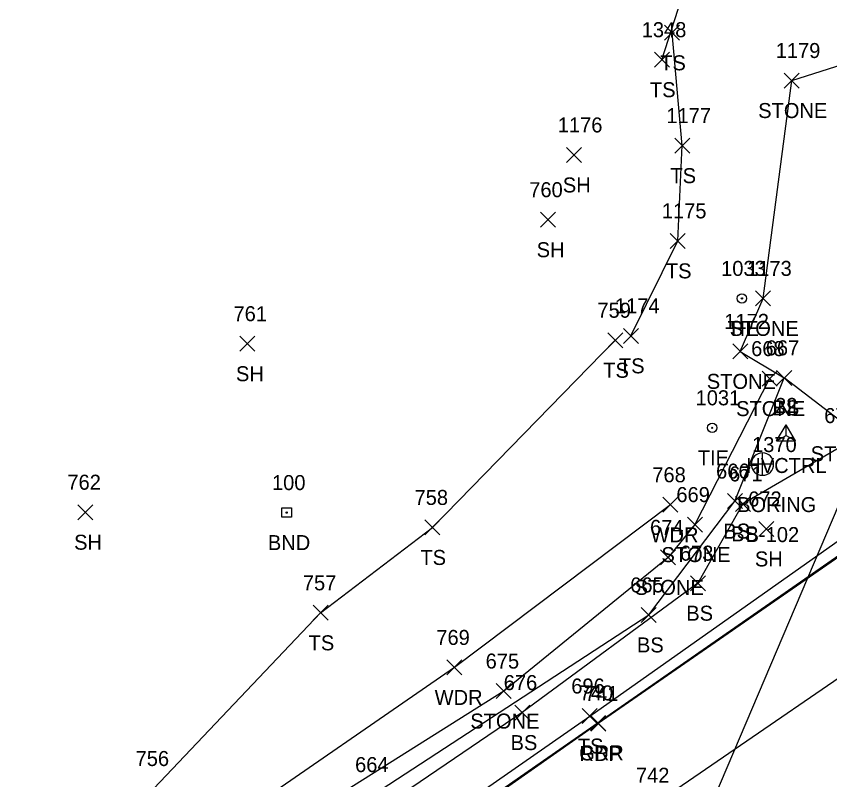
# Model space of a CAD drawing. Extents: x 1528286 to 1556263, y 492387 to 508952.
# Drawn here: x 1528575.8 to 1528684.2, y 492794 to 492895.8 of the extents above; entities that cross this region are included whole.
import ezdxf

# ---------------------------------------------------------------- set-up
doc = ezdxf.new("R2010")
doc.units = 0
for name, color, linetype in [('C_A', 7, 'Continuous'), ('C_I', 7, 'Continuous'), ('CBP', 7, 'Continuous'), ('CPSM', 7, 'Continuous'), ('DCP', 7, 'Continuous'), ('G_A', 7, 'Continuous'), ('G_C', 7, 'Continuous'), ('G_I', 7, 'Continuous'), ('GA_P', 7, 'Continuous'), ('L_A', 7, 'Continuous'), ('L_I', 7, 'Continuous'), ('L_TIC', 7, 'Continuous'), ('LASF', 7, 'Continuous'), ('LAWA', 7, 'Continuous'), ('LELB', 7, 'Continuous'), ('Level 18', 7, 'Continuous'), ('M_A', 7, 'Continuous'), ('M_I', 7, 'Continuous'), ('P_A', 7, 'Continuous'), ('P_I', 7, 'Continuous'), ('P_TIC', 7, 'Continuous'), ('PET', 7, 'Continuous'), ('PRC', 7, 'Continuous'), ('R_A', 7, 'Continuous'), ('R_I', 7, 'Continuous'), ('R_TIC', 7, 'Continuous'), ('RGR', 7, 'Continuous')]:
    doc.layers.add(name, color=color, linetype=linetype)

msp = doc.modelspace()

# ---------------------------------------------------------------- linework, layer by layer
at = {"layer": 'CBP'}
for centre, radius in [((1528672.47, 492858.2), 0.625), ((1528672.47, 492858.2), 0.625), ((1528672.47, 492858.2), 0.0833), ((1528672.47, 492858.2), 0.0833), ((1528668.51, 492840.95), 0.625), ((1528668.51, 492840.95), 0.625), ((1528668.51, 492840.95), 0.0833), ((1528668.51, 492840.95), 0.0833)]:
    msp.add_circle(centre, radius, dxfattribs=at)
at = {"layer": 'CPSM'}
for p, q in [((1528677.1, 492839.21), (1528678.35, 492841.37)), ((1528677.1, 492839.21), (1528678.35, 492841.37)), ((1528679.6, 492839.21), (1528678.35, 492841.37)), ((1528678.36, 492839.93), (1528678.35, 492841.37)), ((1528679.6, 492839.21), (1528678.35, 492841.37)), ((1528678.36, 492839.93), (1528678.35, 492841.37)), ((1528677.1, 492839.21), (1528678.36, 492839.93)), ((1528677.1, 492839.21), (1528678.36, 492839.93)), ((1528678.36, 492839.93), (1528678.36, 492839.93)), ((1528678.36, 492839.93), (1528679.6, 492839.21)), ((1528678.36, 492839.93), (1528678.36, 492839.93)), ((1528678.36, 492839.93), (1528679.6, 492839.21)), ((1528677.1, 492839.21), (1528679.6, 492839.21)), ((1528677.1, 492839.21), (1528679.6, 492839.21))]:
    msp.add_line(p, q, dxfattribs=at)
at = {"layer": 'DCP'}
msp.add_lwpolyline([(1528644.2, 492733.84), (1528697.66, 492859.59)], dxfattribs=at)
msp.add_lwpolyline([(1528644.2, 492733.84), (1528697.66, 492859.59)], dxfattribs=at)
at = {"layer": 'GA_P'}
for p, q in [((1528675.2, 492836.12), (1528675.2, 492837.62)), ((1528675.2, 492836.12), (1528675.2, 492837.62)), ((1528675.2, 492836.12), (1528673.7, 492836.12)), ((1528675.2, 492836.12), (1528673.7, 492836.12)), ((1528676.7, 492836.12), (1528675.2, 492836.12)), ((1528675.2, 492834.62), (1528675.2, 492836.12)), ((1528676.7, 492836.12), (1528675.2, 492836.12)), ((1528675.2, 492834.62), (1528675.2, 492836.12))]:
    msp.add_line(p, q, dxfattribs=at)
for start, end in [(90, 180), (90, 180), (0, 90), (0, 90), (180, 270), (180, 270), (270, 0), (270, 0)]:
    msp.add_arc((1528675.2, 492836.12), 1.5, start, end, dxfattribs=at)
at = {"layer": 'L_TIC'}
for points in [[(1528662.17, 492892.6), (1528664.17, 492894.6)], [(1528664.17, 492892.6), (1528662.17, 492894.6)], [(1528662.17, 492892.6), (1528664.17, 492894.6)], [(1528664.17, 492892.6), (1528662.17, 492894.6)], [(1528660.81, 492889.02), (1528662.81, 492891.02)], [(1528662.81, 492889.02), (1528660.81, 492891.02)], [(1528660.81, 492889.02), (1528662.81, 492891.02)], [(1528662.81, 492889.02), (1528660.81, 492891.02)], [(1528678.1, 492886.24), (1528680.1, 492888.24)], [(1528680.1, 492886.24), (1528678.1, 492888.24)], [(1528678.1, 492886.24), (1528680.1, 492888.24)], [(1528680.1, 492886.24), (1528678.1, 492888.24)], [(1528663.53, 492877.56), (1528665.53, 492879.56)], [(1528665.53, 492877.56), (1528663.53, 492879.56)], [(1528663.53, 492877.56), (1528665.53, 492879.56)], [(1528665.53, 492877.56), (1528663.53, 492879.56)], [(1528649.12, 492876.32), (1528651.12, 492878.32)], [(1528651.12, 492876.32), (1528649.12, 492878.32)], [(1528649.12, 492876.32), (1528651.12, 492878.32)], [(1528651.12, 492876.32), (1528649.12, 492878.32)], [(1528645.64, 492867.69), (1528647.64, 492869.69)], [(1528647.64, 492867.69), (1528645.64, 492869.69)], [(1528645.64, 492867.69), (1528647.64, 492869.69)], [(1528647.64, 492867.69), (1528645.64, 492869.69)], [(1528662.93, 492864.87), (1528664.93, 492866.87)], [(1528664.93, 492864.87), (1528662.93, 492866.87)], [(1528662.93, 492864.87), (1528664.93, 492866.87)], [(1528664.93, 492864.87), (1528662.93, 492866.87)], [(1528674.29, 492857.2), (1528676.29, 492859.2)], [(1528676.29, 492857.2), (1528674.29, 492859.2)], [(1528674.29, 492857.2), (1528676.29, 492859.2)], [(1528676.29, 492857.2), (1528674.29, 492859.2)], [(1528656.68, 492852.21), (1528658.68, 492854.21)], [(1528658.68, 492852.21), (1528656.68, 492854.21)], [(1528656.68, 492852.21), (1528658.68, 492854.21)], [(1528658.68, 492852.21), (1528656.68, 492854.21)], [(1528605.58, 492851.16), (1528607.58, 492853.16)], [(1528607.58, 492851.16), (1528605.58, 492853.16)], [(1528605.58, 492851.16), (1528607.58, 492853.16)], [(1528607.58, 492851.16), (1528605.58, 492853.16)], [(1528654.59, 492851.62), (1528656.59, 492853.62)], [(1528656.59, 492851.62), (1528654.59, 492853.62)], [(1528654.59, 492851.62), (1528656.59, 492853.62)], [(1528656.59, 492851.62), (1528654.59, 492853.62)], [(1528671.24, 492850.14), (1528673.24, 492852.14)], [(1528673.24, 492850.14), (1528671.24, 492852.14)], [(1528671.24, 492850.14), (1528673.24, 492852.14)], [(1528673.24, 492850.14), (1528671.24, 492852.14)], [(1528677.1, 492846.61), (1528679.1, 492848.61)], [(1528679.1, 492846.61), (1528677.1, 492848.61)], [(1528677.1, 492846.61), (1528679.1, 492848.61)], [(1528679.1, 492846.61), (1528677.1, 492848.61)], [(1528675.16, 492846.51), (1528677.16, 492848.51)], [(1528677.16, 492846.51), (1528675.16, 492848.51)], [(1528675.16, 492846.51), (1528677.16, 492848.51)], [(1528677.16, 492846.51), (1528675.16, 492848.51)], [(1528661.94, 492829.69), (1528663.94, 492831.69)], [(1528663.94, 492829.69), (1528661.94, 492831.69)], [(1528661.94, 492829.69), (1528663.94, 492831.69)], [(1528663.94, 492829.69), (1528661.94, 492831.69)], [(1528670.54, 492830.18), (1528672.54, 492832.18)], [(1528672.54, 492830.18), (1528670.54, 492832.18)], [(1528670.54, 492830.18), (1528672.54, 492832.18)], [(1528672.54, 492830.18), (1528670.54, 492832.18)], [(1528671.61, 492829.81), (1528673.61, 492831.81)], [(1528673.61, 492829.81), (1528671.61, 492831.81)], [(1528671.61, 492829.81), (1528673.61, 492831.81)], [(1528673.61, 492829.81), (1528671.61, 492831.81)], [(1528584.02, 492828.7), (1528586.02, 492830.7)], [(1528586.02, 492828.7), (1528584.02, 492830.7)], [(1528584.02, 492828.7), (1528586.02, 492830.7)], [(1528586.02, 492828.7), (1528584.02, 492830.7)], [(1528630.23, 492826.67), (1528632.23, 492828.67)], [(1528632.23, 492826.67), (1528630.23, 492828.67)], [(1528630.23, 492826.67), (1528632.23, 492828.67)], [(1528632.23, 492826.67), (1528630.23, 492828.67)], [(1528665.2, 492827.05), (1528667.2, 492829.05)], [(1528667.2, 492827.05), (1528665.2, 492829.05)], [(1528665.2, 492827.05), (1528667.2, 492829.05)], [(1528667.2, 492827.05), (1528665.2, 492829.05)], [(1528674.71, 492826.47), (1528676.71, 492828.47)], [(1528676.71, 492826.47), (1528674.71, 492828.47)], [(1528674.71, 492826.47), (1528676.71, 492828.47)], [(1528676.71, 492826.47), (1528674.71, 492828.47)], [(1528661.64, 492822.68), (1528663.64, 492824.68)], [(1528663.64, 492822.68), (1528661.64, 492824.68)], [(1528661.64, 492822.68), (1528663.64, 492824.68)], [(1528663.64, 492822.68), (1528661.64, 492824.68)], [(1528665.62, 492819.24), (1528667.62, 492821.24)], [(1528667.62, 492819.24), (1528665.62, 492821.24)], [(1528665.62, 492819.24), (1528667.62, 492821.24)], [(1528667.62, 492819.24), (1528665.62, 492821.24)], [(1528615.34, 492815.29), (1528617.34, 492817.29)], [(1528617.34, 492815.29), (1528615.34, 492817.29)], [(1528615.34, 492815.29), (1528617.34, 492817.29)], [(1528617.34, 492815.29), (1528615.34, 492817.29)], [(1528659.05, 492815.01), (1528661.05, 492817.01)], [(1528661.05, 492815.01), (1528659.05, 492817.01)], [(1528659.05, 492815.01), (1528661.05, 492817.01)], [(1528661.05, 492815.01), (1528659.05, 492817.01)], [(1528633.18, 492808.01), (1528635.18, 492810.01)], [(1528635.18, 492808.01), (1528633.18, 492810.01)], [(1528633.18, 492808.01), (1528635.18, 492810.01)], [(1528635.18, 492808.01), (1528633.18, 492810.01)], [(1528639.74, 492804.86), (1528641.74, 492806.86)], [(1528641.74, 492804.86), (1528639.74, 492806.86)], [(1528639.74, 492804.86), (1528641.74, 492806.86)], [(1528641.74, 492804.86), (1528639.74, 492806.86)], [(1528642.21, 492801.99), (1528644.21, 492803.99)], [(1528644.21, 492801.99), (1528642.21, 492803.99)], [(1528642.21, 492801.99), (1528644.21, 492803.99)], [(1528644.21, 492801.99), (1528642.21, 492803.99)], [(1528651.2, 492801.53), (1528653.2, 492803.53)], [(1528653.2, 492801.53), (1528651.2, 492803.53)], [(1528651.2, 492801.53), (1528653.2, 492803.53)], [(1528653.2, 492801.53), (1528651.2, 492803.53)]]:
    msp.add_lwpolyline(points, dxfattribs=at)
at = {"layer": 'LASF'}
for points in [[(1528672.24, 492851.14), (1528675.29, 492858.2), (1528679.1, 492887.24), (1528690.96, 492891.02), (1528695.31, 492889.33), (1528691.61, 492862.53)], [(1528672.24, 492851.14), (1528675.29, 492858.2), (1528679.1, 492887.24), (1528690.96, 492891.02), (1528695.31, 492889.33), (1528691.61, 492862.53)], [(1528672.24, 492851.14), (1528678.1, 492847.61)], [(1528672.24, 492851.14), (1528678.1, 492847.61)], [(1528676.16, 492847.51), (1528666.2, 492828.05), (1528662.64, 492823.68), (1528640.74, 492805.86), (1528611.48, 492787.39), (1528588.51, 492771.6), (1528589.32, 492769.92)], [(1528676.16, 492847.51), (1528666.2, 492828.05), (1528662.64, 492823.68), (1528640.74, 492805.86), (1528611.48, 492787.39), (1528588.51, 492771.6), (1528589.32, 492769.92)], [(1528686.09, 492841.49), (1528678.1, 492847.61)], [(1528686.09, 492841.49), (1528678.1, 492847.61)]]:
    msp.add_lwpolyline(points, dxfattribs=at)
at = {"layer": 'LAWA'}
msp.add_lwpolyline([(1528662.94, 492830.69), (1528634.18, 492809.01), (1528604.19, 492788.28), (1528566.96, 492760.01), (1528530.31, 492736.52), (1528502.64, 492712.53), (1528486.78, 492718.4), (1528471.22, 492734.89)], dxfattribs=at)
msp.add_lwpolyline([(1528662.94, 492830.69), (1528634.18, 492809.01), (1528604.19, 492788.28), (1528566.96, 492760.01), (1528530.31, 492736.52), (1528502.64, 492712.53), (1528486.78, 492718.4), (1528471.22, 492734.89)], dxfattribs=at)
at = {"layer": 'LELB'}
for points in [[(1528511.53, 492702.85), (1528534.14, 492721.31), (1528572.64, 492751.16), (1528586.73, 492763.59), (1528600.5, 492766.35), (1528613.46, 492775.52), (1528652.2, 492802.53), (1528688.62, 492828.26), (1528710.29, 492843.12), (1528742.91, 492866.47), (1528778.71, 492891.27), (1528817.45, 492919.08), (1528857.75, 492946.94), (1528897.37, 492973.98), (1528940.29, 493003.74)], [(1528511.53, 492702.85), (1528534.14, 492721.31), (1528572.64, 492751.16), (1528586.73, 492763.59), (1528600.5, 492766.35), (1528613.46, 492775.52), (1528652.2, 492802.53), (1528688.62, 492828.26), (1528710.29, 492843.12), (1528742.91, 492866.47), (1528778.71, 492891.27), (1528817.45, 492919.08), (1528857.75, 492946.94), (1528897.37, 492973.98), (1528940.29, 493003.74)], [(1528661.81, 492890.02), (1528672.21, 492922.28), (1528667.05, 492924.05), (1528644.6, 492935.3)], [(1528661.81, 492890.02), (1528672.21, 492922.28), (1528667.05, 492924.05), (1528644.6, 492935.3)], [(1528657.68, 492853.21), (1528663.93, 492865.87), (1528664.53, 492878.56), (1528663.17, 492893.6)], [(1528657.68, 492853.21), (1528663.93, 492865.87), (1528664.53, 492878.56), (1528663.17, 492893.6)], [(1528479.27, 492740.39), (1528490.26, 492728.47), (1528495.22, 492727.6), (1528516.65, 492745.84), (1528531.02, 492756.16), (1528553.24, 492773.68), (1528563.71, 492774.04), (1528594.12, 492792.87), (1528616.34, 492816.29), (1528631.23, 492827.67), (1528655.59, 492852.62)], [(1528479.27, 492740.39), (1528490.26, 492728.47), (1528495.22, 492727.6), (1528516.65, 492745.84), (1528531.02, 492756.16), (1528553.24, 492773.68), (1528563.71, 492774.04), (1528594.12, 492792.87), (1528616.34, 492816.29), (1528631.23, 492827.67), (1528655.59, 492852.62)], [(1528476.47, 492733.09), (1528490.63, 492720.26), (1528499.34, 492715.31), (1528510.27, 492713.09), (1528516.41, 492713.29), (1528530.47, 492725.99), (1528568.48, 492754.56), (1528582.5, 492766.12), (1528590.7, 492769.85), (1528623.39, 492792.06), (1528660.05, 492816.01), (1528671.54, 492831.18), (1528678.1, 492847.61)], [(1528476.47, 492733.09), (1528490.63, 492720.26), (1528499.34, 492715.31), (1528510.27, 492713.09), (1528516.41, 492713.29), (1528530.47, 492725.99), (1528568.48, 492754.56), (1528582.5, 492766.12), (1528590.7, 492769.85), (1528623.39, 492792.06), (1528660.05, 492816.01), (1528671.54, 492831.18), (1528678.1, 492847.61)], [(1528685.94, 492838.58), (1528672.61, 492830.81), (1528666.62, 492820.24), (1528643.21, 492802.99), (1528614.9, 492783.77), (1528590.5, 492768.83), (1528580.05, 492763.59), (1528573.99, 492757.65), (1528555.82, 492743.68), (1528531.3, 492723.9), (1528516.93, 492710.51), (1528511.37, 492706.6)], [(1528685.94, 492838.58), (1528672.61, 492830.81), (1528666.62, 492820.24), (1528643.21, 492802.99), (1528614.9, 492783.77), (1528590.5, 492768.83), (1528580.05, 492763.59), (1528573.99, 492757.65), (1528555.82, 492743.68), (1528531.3, 492723.9), (1528516.93, 492710.51), (1528511.37, 492706.6)]]:
    msp.add_lwpolyline(points, dxfattribs=at)
at = {"layer": 'Level 18'}
msp.add_lwpolyline([(1528611.2, 492830.28), (1528612.45, 492830.28), (1528612.45, 492829.03), (1528611.2, 492829.03)], close=True, dxfattribs=at)
msp.add_lwpolyline([(1528611.2, 492830.28), (1528612.45, 492830.28), (1528612.45, 492829.03), (1528611.2, 492829.03)], close=True, dxfattribs=at)
msp.add_circle((1528611.83, 492829.65), 0.0833, dxfattribs=at)
msp.add_circle((1528611.83, 492829.65), 0.0833, dxfattribs=at)
at = {"layer": 'P_TIC'}
for points in [[(1528652.33, 492800.52), (1528654.33, 492802.52)], [(1528654.33, 492800.52), (1528652.33, 492802.52)], [(1528652.33, 492800.52), (1528654.33, 492802.52)], [(1528654.33, 492800.52), (1528652.33, 492802.52)]]:
    msp.add_lwpolyline(points, dxfattribs=at)
at = {"layer": 'PET'}
for points in [[(1528942, 493002.12), (1528898.48, 492972.51), (1528859.28, 492945.34), (1528819.08, 492917.53), (1528787.55, 492894.48), (1528780.46, 492889.94), (1528744.23, 492865.12), (1528711.17, 492841.82), (1528689.56, 492826.66), (1528653.33, 492801.52)], [(1528942, 493002.12), (1528898.48, 492972.51), (1528859.28, 492945.34), (1528819.08, 492917.53), (1528787.55, 492894.48), (1528780.46, 492889.94), (1528744.23, 492865.12), (1528711.17, 492841.82), (1528689.56, 492826.66), (1528653.33, 492801.52)], [(1528653.33, 492801.52), (1528614.2, 492774.09)], [(1528653.33, 492801.52), (1528614.2, 492774.09)]]:
    msp.add_lwpolyline(points, dxfattribs=at)
at = {"layer": 'PRC'}
msp.add_lwpolyline([(1528788.69, 492878.6), (1528752.94, 492854.08), (1528719.05, 492830.75), (1528697.88, 492816.16), (1528660.71, 492790.64)], dxfattribs=at)
msp.add_lwpolyline([(1528788.69, 492878.6), (1528752.94, 492854.08), (1528719.05, 492830.75), (1528697.88, 492816.16), (1528660.71, 492790.64)], dxfattribs=at)
at = {"layer": 'R_TIC'}
for points in [[(1528652.3, 492800.62), (1528654.3, 492802.62)], [(1528654.3, 492800.62), (1528652.3, 492802.62)], [(1528652.3, 492800.62), (1528654.3, 492802.62)], [(1528654.3, 492800.62), (1528652.3, 492802.62)]]:
    msp.add_lwpolyline(points, dxfattribs=at)
at = {"layer": 'RGR'}
for points in [[(1528941.4, 493002.79), (1528898.12, 492973.22), (1528858.97, 492945.9), (1528818.83, 492918.12), (1528780.05, 492890.64), (1528744.15, 492865.31), (1528711.24, 492842.07), (1528689.6, 492826.87), (1528653.3, 492801.62)], [(1528941.4, 493002.79), (1528898.12, 492973.22), (1528858.97, 492945.9), (1528818.83, 492918.12), (1528780.05, 492890.64), (1528744.15, 492865.31), (1528711.24, 492842.07), (1528689.6, 492826.87), (1528653.3, 492801.62)], [(1528653.3, 492801.62), (1528614.13, 492774.35)], [(1528653.3, 492801.62), (1528614.13, 492774.35)]]:
    msp.add_lwpolyline(points, dxfattribs=at)

# ---------------------------------------------------------------- texts
at = {"layer": 'C_A'}
for s, p in [('TIE', (1528670.55, 492853.2)), ('TIE', (1528670.55, 492853.2)), ('TIE', (1528666.59, 492835.95)), ('TIE', (1528666.59, 492835.95)), ('HVCTRL', (1528673.05, 492834.93)), ('HVCTRL', (1528673.05, 492834.93))]:
    msp.add_text(s, height=2, dxfattribs=at).set_placement(p)
at = {"layer": 'C_I'}
for s, p in [('1033', (1528669.7, 492861.2)), ('1033', (1528669.7, 492861.2)), ('1031', (1528666.3, 492843.95)), ('1031', (1528666.3, 492843.95)), ('22', (1528676.89, 492842.93)), ('22', (1528676.89, 492842.93))]:
    msp.add_text(s, height=2, dxfattribs=at).set_placement(p)
at = {"layer": 'G_A'}
msp.add_text('BORING', height=2, dxfattribs=at).set_placement((1528671.83, 492829.72))
msp.add_text('BORING', height=2, dxfattribs=at).set_placement((1528671.83, 492829.72))
at = {"layer": 'G_C'}
msp.add_text('B-102', height=2, dxfattribs=at).set_placement((1528672.96, 492825.72))
msp.add_text('B-102', height=2, dxfattribs=at).set_placement((1528672.96, 492825.72))
at = {"layer": 'G_I'}
msp.add_text('1370', height=2, dxfattribs=at).set_placement((1528673.82, 492837.72))
msp.add_text('1370', height=2, dxfattribs=at).set_placement((1528673.82, 492837.72))
at = {"layer": 'L_A'}
for s, p in [('TS', (1528661.58, 492888.6)), ('TS', (1528661.58, 492888.6)), ('TS', (1528660.22, 492885.02)), ('TS', (1528660.22, 492885.02)), ('STONE', (1528674.64, 492882.24)), ('STONE', (1528674.64, 492882.24)), ('TS', (1528662.94, 492873.56)), ('TS', (1528662.94, 492873.56)), ('SH', (1528648.61, 492872.32)), ('SH', (1528648.61, 492872.32)), ('SH', (1528645.13, 492863.69)), ('SH', (1528645.13, 492863.69)), ('TS', (1528662.34, 492860.87)), ('TS', (1528662.34, 492860.87)), ('STONE', (1528670.83, 492853.2)), ('STONE', (1528670.83, 492853.2)), ('TS', (1528656.09, 492848.21)), ('TS', (1528656.09, 492848.21)), ('SH', (1528605.07, 492847.16)), ('SH', (1528605.07, 492847.16)), ('TS', (1528654, 492847.62)), ('TS', (1528654, 492847.62)), ('STONE', (1528667.79, 492846.14)), ('STONE', (1528667.79, 492846.14)), ('STONE', (1528671.7, 492842.51)), ('STONE', (1528671.7, 492842.51)), ('BS', (1528676.54, 492842.61)), ('BS', (1528676.54, 492842.61)), ('STONE', (1528681.63, 492836.49)), ('STONE', (1528681.63, 492836.49)), ('BS', (1528669.98, 492826.18)), ('BS', (1528669.98, 492826.18)), ('WDR', (1528660.3, 492825.69)), ('WDR', (1528660.3, 492825.69)), ('BS', (1528671.05, 492825.81)), ('BS', (1528671.05, 492825.81)), ('SH', (1528583.51, 492824.7)), ('SH', (1528583.51, 492824.7)), ('STONE', (1528661.75, 492823.05)), ('STONE', (1528661.75, 492823.05)), ('TS', (1528629.64, 492822.67)), ('TS', (1528629.64, 492822.67)), ('SH', (1528674.2, 492822.47)), ('SH', (1528674.2, 492822.47)), ('STONE', (1528658.18, 492818.68)), ('STONE', (1528658.18, 492818.68)), ('BS', (1528665.06, 492815.24)), ('BS', (1528665.06, 492815.24)), ('TS', (1528614.75, 492811.29)), ('TS', (1528614.75, 492811.29)), ('BS', (1528658.49, 492811.01)), ('BS', (1528658.49, 492811.01)), ('WDR', (1528631.54, 492804.01)), ('WDR', (1528631.54, 492804.01)), ('STONE', (1528636.29, 492800.86)), ('STONE', (1528636.29, 492800.86)), ('BS', (1528641.65, 492797.99)), ('BS', (1528641.65, 492797.99)), ('TS', (1528650.61, 492797.53)), ('TS', (1528650.61, 492797.53))]:
    msp.add_text(s, height=2, dxfattribs=at).set_placement(p)
at = {"layer": 'L_I'}
for s, p in [('1348', (1528659.12, 492893.02)), ('1348', (1528659.12, 492893.02)), ('1179', (1528676.97, 492890.24)), ('1179', (1528676.97, 492890.24)), ('1177', (1528662.4, 492881.56)), ('1177', (1528662.4, 492881.56)), ('1176', (1528647.94, 492880.32)), ('1176', (1528647.94, 492880.32)), ('760', (1528644.14, 492871.69)), ('760', (1528644.14, 492871.69)), ('1175', (1528661.8, 492868.87)), ('1175', (1528661.8, 492868.87)), ('1173', (1528673.16, 492861.2)), ('1173', (1528673.16, 492861.2)), ('759', (1528653.22, 492855.62)), ('759', (1528653.22, 492855.62)), ('1174', (1528655.55, 492856.21)), ('1174', (1528655.55, 492856.21)), ('761', (1528604.74, 492855.16)), ('761', (1528604.74, 492855.16)), ('1172', (1528670.12, 492854.14)), ('1172', (1528670.12, 492854.14)), ('668', (1528673.7, 492850.51)), ('668', (1528673.7, 492850.51)), ('667', (1528675.64, 492850.61)), ('667', (1528675.64, 492850.61)), ('670', (1528683.44, 492841.58)), ('670', (1528683.44, 492841.58)), ('768', (1528660.53, 492833.69)), ('768', (1528660.53, 492833.69)), ('666', (1528669.03, 492834.18)), ('666', (1528669.03, 492834.18)), ('671', (1528670.76, 492833.81)), ('671', (1528670.76, 492833.81)), ('762', (1528582.61, 492832.7)), ('762', (1528582.61, 492832.7)), ('758', (1528628.86, 492830.67)), ('758', (1528628.86, 492830.67)), ('669', (1528663.74, 492831.05)), ('669', (1528663.74, 492831.05)), ('672', (1528673.3, 492830.47)), ('672', (1528673.3, 492830.47)), ('674', (1528660.23, 492826.68)), ('674', (1528660.23, 492826.68)), ('673', (1528664.21, 492823.24)), ('673', (1528664.21, 492823.24)), ('757', (1528613.98, 492819.29)), ('757', (1528613.98, 492819.29)), ('665', (1528657.59, 492819.01)), ('665', (1528657.59, 492819.01)), ('769', (1528631.76, 492812.01)), ('769', (1528631.76, 492812.01)), ('675', (1528638.33, 492808.86)), ('675', (1528638.33, 492808.86)), ('676', (1528640.74, 492805.99)), ('676', (1528640.74, 492805.99)), ('696', (1528649.74, 492805.53)), ('696', (1528649.74, 492805.53)), ('756', (1528591.7, 492795.87)), ('756', (1528591.7, 492795.87)), ('664', (1528620.94, 492795.06)), ('664', (1528620.94, 492795.06))]:
    msp.add_text(s, height=2, dxfattribs=at).set_placement(p)
at = {"layer": 'M_A'}
msp.add_text('BND', height=2, dxfattribs=at).set_placement((1528609.32, 492824.65))
msp.add_text('BND', height=2, dxfattribs=at).set_placement((1528609.32, 492824.65))
at = {"layer": 'M_I'}
msp.add_text('100', height=2, dxfattribs=at).set_placement((1528609.87, 492832.65))
msp.add_text('100', height=2, dxfattribs=at).set_placement((1528609.87, 492832.65))
at = {"layer": 'P_A'}
msp.add_text('RDP', height=2, dxfattribs=at).set_placement((1528650.82, 492796.52))
msp.add_text('RDP', height=2, dxfattribs=at).set_placement((1528650.82, 492796.52))
at = {"layer": 'P_I'}
for s, p in [('741', (1528651.54, 492804.52)), ('741', (1528651.54, 492804.52)), ('742', (1528658.35, 492793.64)), ('742', (1528658.35, 492793.64))]:
    msp.add_text(s, height=2, dxfattribs=at).set_placement(p)
at = {"layer": 'R_A'}
msp.add_text('GRR', height=2, dxfattribs=at).set_placement((1528650.79, 492796.62))
msp.add_text('GRR', height=2, dxfattribs=at).set_placement((1528650.79, 492796.62))
at = {"layer": 'R_I'}
msp.add_text('740', height=2, dxfattribs=at).set_placement((1528650.85, 492804.62))
msp.add_text('740', height=2, dxfattribs=at).set_placement((1528650.85, 492804.62))

doc.saveas('drawing.dxf')
